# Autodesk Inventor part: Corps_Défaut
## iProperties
Shininess: 64.0
Length Units: 11269
Angle Units: 11279
Time Units: 11290
Mass Units: 11283
Length Display Precision: 3
Angle Display Precision: 2
Compacted: True
Part Number: Corps_Défaut
Document SubType Name: Modeling
Created: 2006-01
Material: Par défaut
Designer: riri
Density: 0.0
Volumn: 0.0
Area: 0.0
PropertySet Name: Model Information
Control State: 0
Master: False
Checked Out: False
Author: riri
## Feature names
1. Base1
